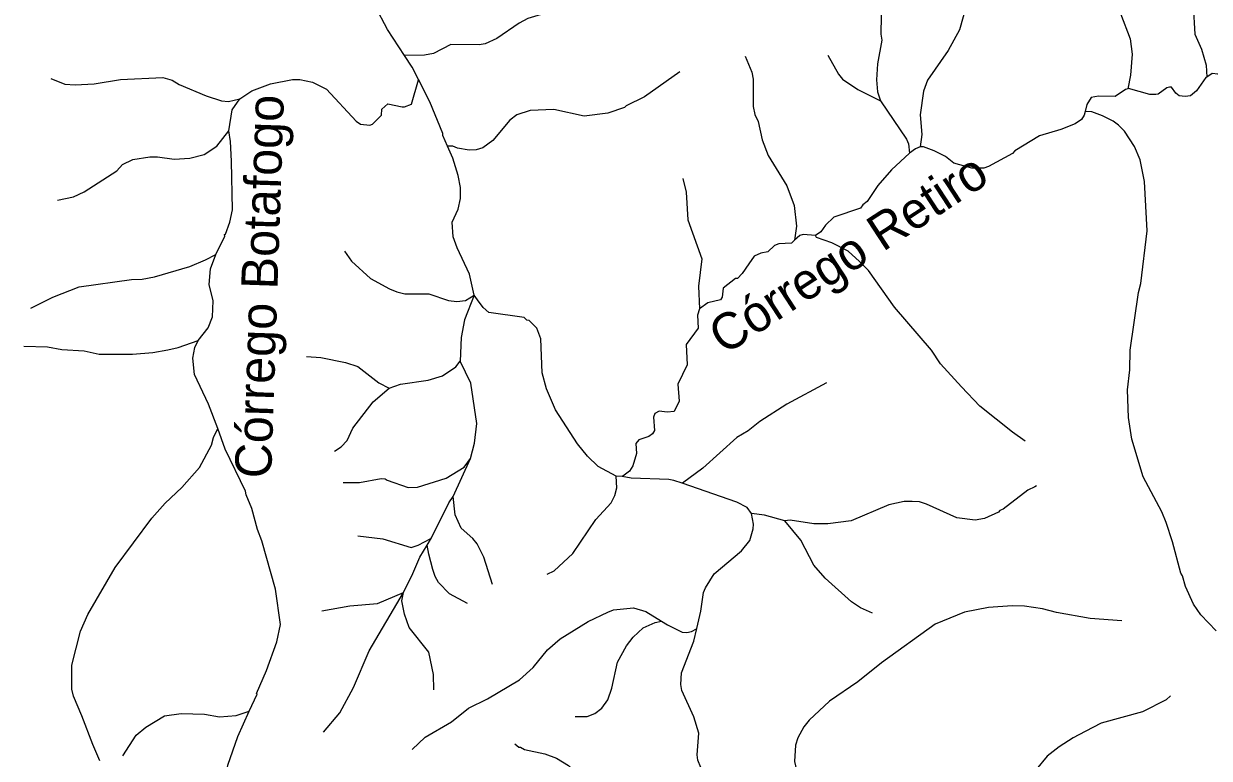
# Model space of a CAD drawing. Extents: x 393 to 446.6, y 8175.5 to 8231.
# Drawn here: x 406.01 to 412.53, y 8199.78 to 8203.82 of the extents above; entities that cross this region are included whole.
import ezdxf
from ezdxf.enums import TextEntityAlignment as Align

# ---------------------------------------------------------------- set-up
doc = ezdxf.new("R2010")
doc.units = 0
doc.header["$LTSCALE"] = 0.064
doc.linetypes.add('LONG_DASHED', pattern=[7.5, 6, -1.5])
doc.layers.add('61', color=7, linetype='Continuous')
doc.layers.add('7', color=7, linetype='Continuous', lineweight=25)
doc.layers.add('9', color=7, linetype='LONG_DASHED', lineweight=25)

msp = doc.modelspace()

# ---------------------------------------------------------------- linework, layer by layer
at = {"layer": '7'}
msp.add_line((409.3006, 8201.3317), (409.2665, 8201.3329), dxfattribs=at)
for points in [[(409.7634, 8204.3886), (409.6653, 8204.3306), (409.6545, 8204.3242), (409.5577, 8204.2434), (409.4091, 8204.132), (409.3219, 8204.0771), (409.2395, 8204.0109), (409.1136, 8203.9382), (409.049, 8203.9172), (408.9521, 8203.9027), (408.781, 8203.851), (408.7325, 8203.8252), (408.6098, 8203.7412), (408.5452, 8203.7121), (408.5129, 8203.7073), (408.3579, 8203.7089), (408.261, 8203.6589), (408.2126, 8203.6508), (408.1038, 8203.648), (408.1028, 8203.648)], [(408.1028, 8203.648), (408.0091, 8203.7913), (407.9413, 8203.9205), (407.9025, 8204.0238), (407.8508, 8204.0997), (407.7975, 8204.1594), (407.7913, 8204.1635)], [(408.179, 8203.5166), (408.1446, 8203.584), (408.1028, 8203.648)], [(409.6166, 8203.5578), (409.4236, 8203.4215), (409.3219, 8203.3714), (409.3122, 8203.3618), (409.2202, 8203.3311), (409.091, 8203.3149), (408.9231, 8203.3504), (408.7939, 8203.3456), (408.7196, 8203.3214), (408.6808, 8203.2923), (408.5888, 8203.1809), (408.5339, 8203.1405), (408.4968, 8203.1292), (408.458, 8203.1276), (408.3934, 8203.1389), (408.3676, 8203.1502), (408.3386, 8203.1498)], [(408.3386, 8203.1498), (408.3127, 8203.2084), (408.3127, 8203.2196), (408.2416, 8203.3941), (408.179, 8203.5166)], [(408.4854, 8202.3295), (408.4596, 8202.4446), (408.3918, 8202.5899), (408.3692, 8202.6513), (408.3643, 8202.7303), (408.3966, 8202.8031), (408.4095, 8202.8612), (408.4095, 8202.9226), (408.3982, 8202.9871), (408.3676, 8203.084), (408.3386, 8203.1498)], [(409.2665, 8201.3329), (409.1669, 8201.3869), (409.1087, 8201.4434), (409.0539, 8201.5112), (408.9327, 8201.6985), (408.8827, 8201.8148), (408.8601, 8201.902), (408.852, 8202.0893), (408.831, 8202.1474), (408.789, 8202.191), (408.7761, 8202.1926), (408.76, 8202.2072), (408.5662, 8202.2346), (408.5355, 8202.2621), (408.5041, 8202.3034), (408.4854, 8202.3295)], [(410.4247, 8201.8475), (410.2052, 8201.7292), (410.0566, 8201.6339), (409.9936, 8201.5839), (409.9307, 8201.5467), (409.7434, 8201.3771), (409.6325, 8201.2957), (409.6308, 8201.2944)], [(408.8872, 8200.7945), (408.9263, 8200.812), (409.028, 8200.9089), (409.1556, 8201.0946), (409.2395, 8201.1866), (409.2589, 8201.227), (409.2702, 8201.269), (409.2665, 8201.3329)], [(409.6308, 8201.2944), (409.585, 8201.3104), (409.5561, 8201.3158), (409.3494, 8201.3223), (409.3006, 8201.3317)], [(410.0107, 8201.1278), (409.9872, 8201.1608), (409.9307, 8201.1899), (409.6308, 8201.2944)], [(411.5802, 8201.2806), (411.5701, 8201.2755), (411.5324, 8201.2562), (411.3969, 8201.1527), (411.3775, 8201.1446), (411.3711, 8201.1349), (411.2936, 8201.101), (411.2419, 8201.0914), (411.1418, 8201.1043), (410.9739, 8201.1801), (410.9351, 8201.1915), (410.8963, 8201.1947), (410.8511, 8201.1947), (410.7672, 8201.1753), (410.5605, 8201.0881), (410.4313, 8201.072), (410.3538, 8201.072), (410.2246, 8201.0913), (410.1943, 8201.0884)], [(409.7104, 8200.495), (409.732, 8200.5908), (409.7466, 8200.6941), (409.7579, 8200.72), (409.8064, 8200.7959), (409.9565, 8200.9234), (410.0017, 8200.9799), (410.0211, 8201.0429), (410.0227, 8201.0688), (410.0107, 8201.1278)], [(410.1943, 8201.0884), (410.0825, 8201.1188), (410.0107, 8201.1278)], [(410.6769, 8200.5789), (410.6121, 8200.6085), (410.5621, 8200.6424), (410.4175, 8200.7723), (410.3554, 8200.8443), (410.2827, 8200.9815), (410.1943, 8201.0884)], [(408.1446, 8199.8296), (408.2158, 8199.898), (408.3611, 8199.982), (408.4548, 8200.0562), (408.5581, 8200.1079), (408.7357, 8200.2129), (408.81, 8200.2807), (408.8891, 8200.3776), (408.9586, 8200.439), (409.1136, 8200.5342), (409.2202, 8200.5859), (409.2525, 8200.5988), (409.3623, 8200.6085), (409.4301, 8200.5891), (409.5166, 8200.5353)], [(412.0495, 8200.5384), (411.8749, 8200.5504), (411.6908, 8200.5827), (411.6133, 8200.6037), (411.5132, 8200.6182), (411.4454, 8200.6198), (411.3162, 8200.6101), (411.1838, 8200.5859), (411.0223, 8200.5197), (410.7268, 8200.3066), (410.5959, 8200.2016), (410.441, 8200.095), (410.3295, 8199.9917), (410.3004, 8199.9546), (410.2665, 8199.8932), (410.2536, 8199.8544), (410.2488, 8199.764), (410.2649, 8199.693), (410.3101, 8199.5686), (410.3166, 8199.4943), (410.2988, 8199.4314), (410.2652, 8199.3784)], [(409.042, 8200.0108), (409.1072, 8200.0108), (409.1491, 8200.0272), (409.1879, 8200.0562), (409.2218, 8200.1031), (409.2428, 8200.1677), (409.2734, 8200.3098), (409.3235, 8200.4002), (409.3606, 8200.4471), (409.4156, 8200.4987), (409.4818, 8200.5278), (409.5166, 8200.5353)], [(409.5166, 8200.5353), (409.5496, 8200.5148), (409.6303, 8200.4745), (409.6562, 8200.4729), (409.682, 8200.4793), (409.7089, 8200.4942), (409.7104, 8200.495)], [(409.6549, 8199.5242), (409.7288, 8199.5944), (409.7514, 8199.6542), (409.7514, 8199.6833), (409.7401, 8199.7268), (409.7336, 8199.7301), (409.7159, 8199.7705), (409.7127, 8199.7995), (409.7224, 8199.919), (409.6933, 8200.0095), (409.6287, 8200.1548), (409.6222, 8200.1871), (409.6271, 8200.2517), (409.6949, 8200.4261), (409.7104, 8200.495)], [(412.3168, 8200.1258), (412.2931, 8200.1031), (412.1623, 8200.0369), (411.9362, 8199.9739), (411.8478, 8199.9279), (411.7812, 8199.8932), (411.7037, 8199.8447), (411.6391, 8199.793), (411.5778, 8199.7204), (411.4534, 8199.5283), (411.4098, 8199.4766), (411.3452, 8199.42), (411.2548, 8199.3571), (411.1805, 8199.3183), (411.0901, 8199.2811), (410.6896, 8199.139), (410.5088, 8199.0179), (410.4061, 8198.9623)], [(408.7087, 8199.8607), (408.7309, 8199.8421), (408.7405, 8199.8431), (408.7616, 8199.8302), (408.8746, 8199.806), (408.9392, 8199.7817), (409.0038, 8199.7414), (409.0426, 8199.7075), (409.1653, 8199.6461), (409.2389, 8199.5992)]]:
    msp.add_lwpolyline(points, dxfattribs=at)
at = {"layer": '9'}
for p, q in [((408.3693, 8201.2218), (408.466, 8201.4305)), ((408.2264, 8200.9543), (408.2499, 8200.9934))]:
    msp.add_line(p, q, dxfattribs=at)
for points in [[(411.2512, 8204.1998), (411.2106, 8204.0313), (411.1967, 8203.9318), (411.1563, 8203.7897), (411.0933, 8203.675), (410.9794, 8203.5133), (410.9572, 8203.4527), (410.9403, 8203.3226), (410.9484, 8203.213), (410.9402, 8203.1456)], [(412.2244, 8204.137), (412.4013, 8204.0061), (412.432, 8203.9528), (412.4417, 8203.9237), (412.4513, 8203.7655), (412.4885, 8203.6831), (412.5127, 8203.5943), (412.5171, 8203.5299)], [(411.8893, 8204.081), (411.9895, 8203.9625), (412.0412, 8203.8785), (412.0961, 8203.7396), (412.1058, 8203.6557), (412.0977, 8203.5394), (412.0815, 8203.4647)], [(410.7271, 8203.9874), (410.7235, 8203.7655), (410.7284, 8203.7332), (410.7058, 8203.6024), (410.6993, 8203.5136), (410.7058, 8203.449), (410.7216, 8203.3988)], [(409.9765, 8203.6449), (410.0127, 8203.5574), (410.0208, 8203.5189), (410.0211, 8203.3682), (410.0308, 8203.323), (410.0486, 8203.2859), (410.0695, 8203.1841), (410.1035, 8203.0985), (410.2068, 8202.9306), (410.2455, 8202.8224), (410.2585, 8202.7094), (410.2489, 8202.632)], [(410.4316, 8203.6502), (410.4906, 8203.5459), (410.5127, 8203.5179), (410.5968, 8203.4607), (410.7216, 8203.3988)], [(412.5171, 8203.5299), (412.5121, 8203.5267), (412.4596, 8203.4543), (412.4269, 8203.4263), (412.3971, 8203.4222), (412.3656, 8203.4269), (412.3469, 8203.4409), (412.3224, 8203.4735), (412.3119, 8203.4747), (412.2967, 8203.47), (412.2495, 8203.4356), (412.2366, 8203.4328), (412.2027, 8203.4328), (412.0856, 8203.466), (412.0815, 8203.4647)], [(412.8378, 8203.4602), (412.8238, 8203.4648), (412.7759, 8203.5045), (412.7152, 8203.536), (412.6738, 8203.5319), (412.6539, 8203.5074), (412.6399, 8203.5016), (412.6212, 8203.5039), (412.5932, 8203.5366), (412.5769, 8203.5459), (412.546, 8203.5488), (412.5171, 8203.5299)], [(406.1558, 8203.5216), (406.2328, 8203.4909), (406.2893, 8203.4877), (406.3943, 8203.4925), (406.5396, 8203.5168), (406.7722, 8203.5265), (406.8238, 8203.5119), (406.8626, 8203.4893), (407.0111, 8203.4263), (407.0951, 8203.3989), (407.1339, 8203.3956), (407.1962, 8203.4105)], [(407.1962, 8203.4105), (407.2622, 8203.4542), (407.3648, 8203.4926), (407.4859, 8203.5168), (407.5263, 8203.5168), (407.5957, 8203.5022), (407.6732, 8203.4635), (407.8363, 8203.2875), (407.8605, 8203.2713), (407.9106, 8203.2649), (407.9267, 8203.2713), (407.9751, 8203.3198), (407.9768, 8203.3537), (408.0107, 8203.3828), (408.0898, 8203.365), (408.1027, 8203.365), (408.1399, 8203.3812), (408.1783, 8203.5142), (408.179, 8203.5166)], [(412.0815, 8203.4647), (412.0704, 8203.4613), (412.0121, 8203.4217), (411.921, 8203.4252), (411.8807, 8203.4165), (411.8562, 8203.378), (411.847, 8203.3396)], [(407.1355, 8203.2343), (407.1542, 8203.3486), (407.1962, 8203.4105)], [(410.7216, 8203.3988), (410.8652, 8203.1877), (410.8763, 8203.1626), (410.8818, 8203.1117)], [(411.847, 8203.3396), (411.8422, 8203.3196), (411.8282, 8203.2963), (411.7932, 8203.2718), (411.7134, 8203.2406), (411.5972, 8203.2067), (411.4615, 8203.1244), (411.4486, 8203.1082), (411.3162, 8203.0372), (411.2904, 8203.0291), (411.2241, 8203.0291), (411.1256, 8203.0566), (411.0788, 8203.0921), (411.0158, 8203.1244), (410.9577, 8203.1454), (410.9402, 8203.1456)], [(412.5693, 8200.4826), (412.4836, 8200.5698), (412.4433, 8200.6295), (412.3997, 8200.7264), (412.3835, 8200.7846), (412.3738, 8200.8007), (412.3286, 8200.9719), (412.2931, 8201.0785), (412.2689, 8201.1382), (412.1671, 8201.3304), (412.1042, 8201.5371), (412.0864, 8201.6566), (412.0799, 8201.8083), (412.0929, 8201.9181), (412.0945, 8202.0263), (412.1413, 8202.3445), (412.1542, 8202.3929), (412.1897, 8202.6836), (412.1736, 8202.9548), (412.1494, 8203.0743), (412.1187, 8203.147), (412.0638, 8203.231), (412.0315, 8203.2649), (412.0025, 8203.2875), (411.9427, 8203.3165), (411.8846, 8203.3375), (411.848, 8203.3395), (411.847, 8203.3396)], [(406.1923, 8202.8518), (406.2813, 8202.8708), (406.3394, 8202.8983), (406.5186, 8203.013), (406.5509, 8203.0485), (406.6074, 8203.0759), (406.7011, 8203.0905), (406.7431, 8203.0905), (406.8351, 8203.0776), (406.9207, 8203.0824), (406.9998, 8203.1034), (407.0692, 8203.1502), (407.1355, 8203.2343)], [(407.0636, 8202.5533), (407.1126, 8202.6546), (407.1112, 8202.6625), (407.1177, 8202.6658), (407.1403, 8202.732), (407.1548, 8202.7998), (407.15, 8203.0663), (407.1451, 8203.1745), (407.1355, 8203.2343)], [(410.9402, 8203.1456), (410.9133, 8203.1339), (410.8818, 8203.1117)], [(410.8818, 8203.1117), (410.7814, 8203.0184), (410.7074, 8202.9338), (410.6477, 8202.845), (410.625, 8202.8272), (410.6121, 8202.8079), (410.4652, 8202.7578), (410.4183, 8202.7142), (410.3925, 8202.6771), (410.3632, 8202.657)], [(409.6341, 8202.9711), (409.6529, 8202.8967), (409.661, 8202.7433), (409.7385, 8202.5301), (409.7208, 8202.3783), (409.7249, 8202.2546)], [(410.2489, 8202.632), (410.2313, 8202.6162), (410.1618, 8202.6121), (410.1385, 8202.6028), (410.1023, 8202.5678), (410.0631, 8202.5608), (410.026, 8202.5447), (409.9968, 8202.5021), (409.9597, 8202.4478), (409.9339, 8202.4219), (409.9226, 8202.4203), (409.8548, 8202.3671), (409.8499, 8202.3186), (409.8418, 8202.3041), (409.7704, 8202.2873), (409.7249, 8202.2546)], [(410.3632, 8202.657), (410.2966, 8202.6629), (410.2768, 8202.657), (410.2489, 8202.632)], [(411.517, 8201.526), (411.4469, 8201.575), (411.2677, 8201.7179), (411.1676, 8201.8245), (411.0513, 8201.952), (411.0029, 8202.0263), (410.7978, 8202.2637), (410.6557, 8202.4655), (410.6056, 8202.5156), (410.5427, 8202.5721), (410.4539, 8202.6173), (410.3689, 8202.6469), (410.3632, 8202.657)], [(406.0451, 8202.258), (406.1666, 8202.3186), (406.3119, 8202.3751), (406.5994, 8202.4155), (406.6591, 8202.4171), (406.7269, 8202.43), (406.9207, 8202.4865), (407.0079, 8202.5237), (407.0636, 8202.5533)], [(406.9665, 8202.0793), (407.0208, 8202.149), (407.045, 8202.2104), (407.0499, 8202.2976), (407.0273, 8202.388), (407.0337, 8202.4736), (407.0636, 8202.5533)], [(407.7716, 8202.5711), (407.8105, 8202.5172), (407.9154, 8202.4219), (408.0203, 8202.3638), (408.0608, 8202.3477), (408.1043, 8202.3364), (408.2352, 8202.3363), (408.3433, 8202.3008), (408.3902, 8202.2944), (408.4386, 8202.3008), (408.4854, 8202.3295)], [(408.4854, 8202.3295), (408.4328, 8202.1942), (408.4141, 8202.0962), (408.4081, 8201.9665)], [(409.7249, 8202.2546), (409.7144, 8202.2196), (409.7179, 8202.1473), (409.6513, 8202.0586), (409.6577, 8201.9456), (409.6061, 8201.839), (409.6142, 8201.7454), (409.5851, 8201.6888), (409.548, 8201.6856), (409.5028, 8201.6921), (409.4789, 8201.6775), (409.4719, 8201.6577), (409.4777, 8201.5854), (409.466, 8201.5667), (409.4474, 8201.5527), (409.3913, 8201.5329), (409.3752, 8201.5128), (409.3784, 8201.4579), (409.359, 8201.3901), (409.3396, 8201.361), (409.3028, 8201.3334), (409.3006, 8201.3317)], [(406.0067, 8202.0498), (406.1369, 8202.0457), (406.2167, 8202.0312), (406.3394, 8202.0231), (406.4217, 8202.0053), (406.6058, 8202.0053), (406.7173, 8202.0134), (406.7996, 8202.0296), (406.8561, 8202.0424), (406.9665, 8202.0793)], [(407.0741, 8201.595), (407.0241, 8201.7292), (406.9465, 8201.8923), (406.9368, 8201.9827), (406.9481, 8202.0409), (406.9665, 8202.0793)], [(407.5622, 8201.9915), (407.6409, 8201.9859), (407.7766, 8201.9585), (407.846, 8201.9375), (407.9606, 8201.8471), (408.0179, 8201.8181)], [(408.0179, 8201.8181), (408.0801, 8201.839), (408.2319, 8201.8616), (408.311, 8201.8859), (408.3837, 8201.9343), (408.4081, 8201.9665)], [(408.466, 8201.4305), (408.4871, 8201.516), (408.5, 8201.6226), (408.4677, 8201.8455), (408.4081, 8201.9665)], [(407.7161, 8201.4719), (407.7539, 8201.495), (407.7862, 8201.529), (407.8185, 8201.5968), (407.9299, 8201.7421), (408.0179, 8201.8181)], [(406.4254, 8199.7672), (406.3878, 8199.8577), (406.3265, 8200.0143), (406.2812, 8200.1225), (406.2715, 8200.1613), (406.2715, 8200.2937), (406.3184, 8200.481), (406.3587, 8200.573), (406.5106, 8200.8314), (406.7124, 8201.1027), (406.785, 8201.185), (406.8771, 8201.2706), (406.974, 8201.3804), (407.0402, 8201.5048), (407.0515, 8201.5467), (407.0724, 8201.5914), (407.0741, 8201.595)], [(407.2479, 8200.0398), (407.2907, 8200.135), (407.2872, 8200.137), (407.3421, 8200.2646), (407.4003, 8200.4228), (407.4197, 8200.5181), (407.3922, 8200.7119), (407.3179, 8200.9783), (407.2937, 8201.0397), (407.2614, 8201.156), (407.2307, 8201.2302), (407.2275, 8201.2512), (407.1161, 8201.4822), (407.0741, 8201.595)], [(407.7637, 8201.299), (407.8541, 8201.298), (407.9736, 8201.3206), (407.9962, 8201.319), (408.0059, 8201.311), (408.1221, 8201.2706), (408.1738, 8201.2722), (408.332, 8201.3222), (408.4305, 8201.3836), (408.466, 8201.4305)], [(408.2499, 8200.9934), (408.3454, 8201.1862), (408.3693, 8201.2218)], [(408.5872, 8200.7369), (408.5387, 8200.8879), (408.5016, 8200.9606), (408.4773, 8200.9912), (408.4144, 8201.0478), (408.3805, 8201.1204), (408.3693, 8201.2218)], [(407.8444, 8201.0051), (407.9833, 8200.9888), (408.1383, 8200.9412), (408.177, 8200.9541), (408.2462, 8200.9914), (408.2499, 8200.9934)], [(408.0962, 8200.6934), (408.1488, 8200.7983), (408.1861, 8200.8882), (408.2264, 8200.9543)], [(408.4482, 8200.6333), (408.3496, 8200.6853), (408.29, 8200.749), (408.2707, 8200.7813), (408.2577, 8200.8201), (408.2351, 8200.9041), (408.2264, 8200.9543)], [(407.6477, 8200.593), (407.8008, 8200.6199), (407.9526, 8200.6328), (408.0962, 8200.6934)], [(407.6557, 8199.9247), (407.7458, 8200.0321), (407.8217, 8200.1709), (407.9073, 8200.3728), (408.0962, 8200.6934)], [(408.2635, 8200.1575), (408.2624, 8200.2414), (408.2351, 8200.3647), (408.1286, 8200.5004), (408.1024, 8200.5745), (408.088, 8200.6472), (408.0962, 8200.6934)], [(406.5515, 8199.7951), (406.6252, 8199.9093), (406.6785, 8199.9529), (406.7818, 8200.0143), (406.8723, 8200.0272), (407.0015, 8200.024), (407.0838, 8200.0095), (407.1759, 8200.0159), (407.2479, 8200.0398)], [(406.9408, 8199.1637), (406.9607, 8199.1976), (406.9578, 8199.2004), (406.9788, 8199.2263), (406.9821, 8199.2424), (407.0159, 8199.3022), (407.0579, 8199.4088), (407.0822, 8199.4895), (407.1015, 8199.5702), (407.1306, 8199.743), (407.1855, 8199.9013), (407.2479, 8200.0398)]]:
    msp.add_lwpolyline(points, dxfattribs=at)

# ---------------------------------------------------------------- texts
at = {"layer": '61'}
for s, rotation, p in [('Córrego Botafogo', 88.07, (407.4034, 8202.3743)), ('Córrego Retiro', 33.132, (410.597, 8202.476))]:
    msp.add_text(s, height=0.2, rotation=rotation, dxfattribs=at).set_placement(p, align=Align.CENTER)

doc.saveas('drawing.dxf')
